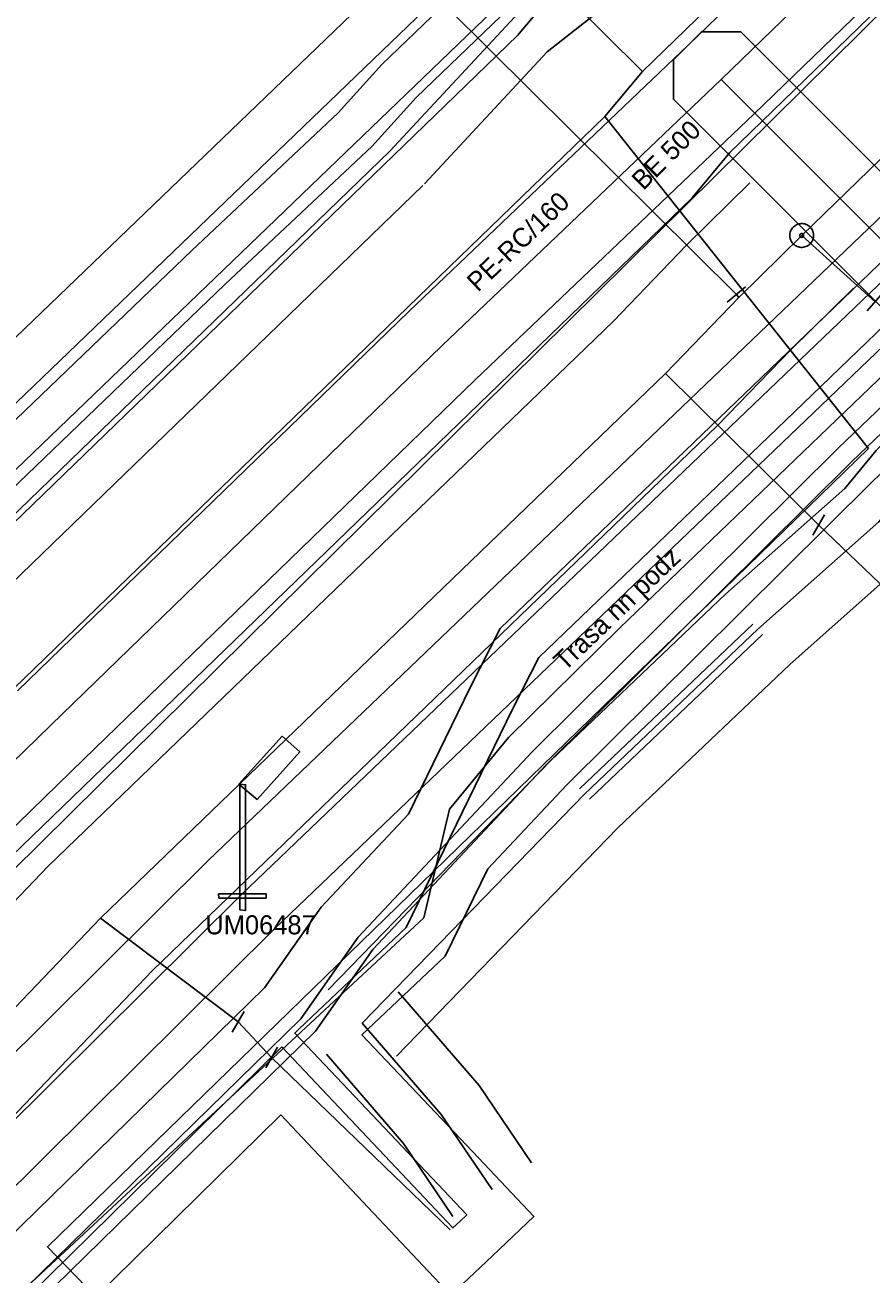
# Model space of a CAD drawing. Extents: x -762993 to -761845, y -975230 to -974501.
# Drawn here: x -762232.71 to -762214.93, y -974970.05 to -974943.8 of the extents above; entities that cross this region are included whole.
import ezdxf

# ---------------------------------------------------------------- set-up
doc = ezdxf.new("R2010")
doc.units = 0
for name, color, linetype in [('IS_CETIN_chranicka', 7, 'Continuous'), ('IS_CETIN_OP', 7, 'Continuous'), ('IS_CETIN_podzem metalika zam', 7, 'Continuous'), ('IS_CETIN_podzem optika zam', 7, 'Continuous'), ('IS_CEZ-D_anotace', 7, 'Continuous'), ('IS_CEZ-D_el vedeni NN podzem', 7, 'Continuous'), ('IS_CEZ-D_el vedeni VN podzem', 7, 'Continuous'), ('IS_CEZ-D_el vedeni VN podzem soubeh investice', 7, 'Continuous'), ('IS_CEZ-D_OP', 7, 'Continuous'), ('IS_CEZ-T_parovod', 7, 'Continuous'), ('IS_CEZ-T_parovod OP', 7, 'Continuous'), ('IS_DPmUL_OP', 7, 'Continuous'), ('IS_DPmUL_VO lampy', 7, 'Continuous'), ('IS_DPmUL_VO lampy anotace', 7, 'Continuous'), ('IS_DPmUL_VO vedeni podzem', 7, 'Continuous'), ('IS_GASNET_plyn NTL anotace', 7, 'Continuous'), ('IS_GASNET_plyn NTL pripojky', 7, 'Continuous'), ('IS_GASNET_plyn NTL rad', 7, 'Continuous'), ('IS_GASNET_plyn OP', 7, 'Continuous'), ('IS_SCVK_kanalizace anotace', 7, 'Continuous'), ('IS_SCVK_kanalizace jednotna', 7, 'Continuous'), ('IS_SCVK_vodovod OP', 7, 'Continuous'), ('IS_SCVK_vodovod pripojky', 7, 'Continuous'), ('IS_SCVK_vodovod privadec', 7, 'Continuous'), ('IS_SCVK_vodovod znaky', 7, 'Continuous'), ('IS_TPS_podzem metalika', 7, 'Continuous')]:
    doc.layers.add(name, color=color, linetype=linetype)

msp = doc.modelspace()

# ---------------------------------------------------------------- linework, layer by layer
at = {"layer": 'IS_CETIN_chranicka'}
for points in [[(-762221.053, -974959.841), (-762217.413, -974956.381)], [(-762220.847, -974960.059), (-762217.207, -974956.599)]]:
    msp.add_lwpolyline(points, dxfattribs=at)
at = {"layer": 'IS_CETIN_OP'}
for points in [[(-762240.314, -974959.621), (-762235.368, -974954.443), (-762229.198, -974948.525), (-762226.125, -974945.639), (-762225.209, -974944.624), (-762223.108, -974942.602)], [(-762220.029, -974943.012), (-762221.734, -974944.362), (-762224.313, -974947.13)], [(-762224.35, -974947.167), (-762239.502, -974961.816), (-762240.717, -974963.012), (-762243.097, -974965.371), (-762252.983, -974975.106)], [(-762211.533, -974949.489), (-762214.818, -974952.733), (-762215.481, -974953.533), (-762217.986, -974955.753), (-762221.653, -974959.239), (-762226.337, -974964.063)], [(-762210.127, -974950.911), (-762213.342, -974954.087), (-762214.039, -974954.927), (-762216.634, -974957.227), (-762220.247, -974960.661), (-762224.903, -974965.457)], [(-762224.864, -974964.106), (-762223.165, -974966.071), (-762222.062, -974967.699)], [(-762226.376, -974965.414), (-762224.755, -974967.289), (-762223.718, -974968.821)]]:
    msp.add_lwpolyline(points, dxfattribs=at)
at = {"layer": 'IS_CETIN_podzem metalika zam'}
for points in [[(-762220.718, -974942.282), (-762222.414, -974943.625), (-762225.045, -974946.448)], [(-762225.045, -974946.448), (-762240.2, -974961.1), (-762241.42, -974962.3), (-762243.8, -974964.66), (-762253.685, -974974.393)], [(-762225.62, -974964.76), (-762223.96, -974966.68), (-762222.89, -974968.26)]]:
    msp.add_lwpolyline(points, dxfattribs=at)
at = {"layer": 'IS_CETIN_podzem optika zam'}
for points in [[(-762240.2, -974960.95), (-762234.66, -974955.15), (-762228.51, -974949.25), (-762225.41, -974946.34), (-762224.49, -974945.32), (-762221.81, -974942.74)], [(-762210.83, -974950.2), (-762214.08, -974953.41), (-762214.76, -974954.23), (-762217.31, -974956.49), (-762220.95, -974959.95), (-762225.62, -974964.76)]]:
    msp.add_lwpolyline(points, dxfattribs=at)
at = {"layer": 'IS_CEZ-D_el vedeni NN podzem'}
for points in [[(-762247.847, -974984.536), (-762246.114, -974982.893), (-762246.05, -974980.697), (-762253.7, -974972.107), (-762252.057, -974970.493), (-762250.973, -974969.428), (-762239.791, -974958.41), (-762235.916, -974954.845), (-762234.541, -974953.31), (-762221.186, -974940.477), (-762220.991, -974940.306), (-762216.22, -974936.128), (-762203.456, -974923.483), (-762203.186, -974923.213), (-762202.673, -974922.708), (-762197.126, -974917.211), (-762182.367, -974902.622)], [(-762208.334, -974953.71), (-762208.48, -974953.847), (-762208.988, -974953.368), (-762212.916, -974949.013), (-762213.196, -974948.702), (-762213.301, -974948.803), (-762216.542, -974951.927), (-762221.91, -974957.079), (-762222.456, -974958.155), (-762224.696, -974962.752), (-762226.947, -974964.881), (-762227.041, -974964.97), (-762223.906, -974968.281), (-762223.426, -974968.788), (-762223.572, -974968.926)], [(-762223.572, -974968.926), (-762223.717, -974969.063), (-762224.197, -974968.555), (-762227.309, -974965.261), (-762240.713, -974978.438), (-762243.49, -974981.054), (-762244.149, -974981.659), (-762244.288, -974981.787), (-762243.667, -974982.434), (-762243.409, -974982.703), (-762244.131, -974983.395)]]:
    msp.add_lwpolyline(points, dxfattribs=at)
at = {"layer": 'IS_CEZ-D_el vedeni VN podzem'}
msp.add_lwpolyline([(-762178.94, -974917.38), (-762180.88, -974919.33), (-762183.85, -974922.18), (-762189.02, -974927.27), (-762191.6, -974929.28), (-762204.29, -974941.85), (-762215.61, -974952.68), (-762222.04, -974959.06), (-762225.71, -974962.96), (-762226.91, -974964.67), (-762236.89, -974974.42), (-762240.73, -974978.21), (-762245.09, -974982.81)], dxfattribs=at)
at = {"layer": 'IS_CEZ-D_el vedeni VN podzem soubeh investice'}
msp.add_lwpolyline([(-762246.655, -974985.018), (-762244.801, -974983.086), (-762240.444, -974978.49), (-762236.61, -974974.705), (-762226.604, -974964.93), (-762225.399, -974963.213), (-762221.753, -974959.339), (-762215.331, -974952.967), (-762204.011, -974942.137), (-762191.335, -974929.581), (-762188.756, -974927.571), (-762183.571, -974922.467), (-762180.6, -974919.615), (-762178.658, -974917.664), (-762169.2, -974908.366)], dxfattribs=at)
at = {"layer": 'IS_CEZ-D_OP'}
for points in [[(-762235.261, -974952.615), (-762221.862, -974939.74), (-762221.65, -974939.554), (-762216.902, -974935.396), (-762204.161, -974922.774), (-762203.89, -974922.503), (-762203.376, -974921.997), (-762197.829, -974916.5), (-762183.107, -974901.948), (-762182.738, -974901.004), (-762180.901, -974896.322), (-762175.443, -974882.405), (-762170.837, -974870.904), (-762171.08, -974867.387), (-762172.169, -974851.621), (-762173.361, -974831.196), (-762173.4, -974830.555), (-762173.438, -974829.89), (-762173.725, -974824.972), (-762174.311, -974821.59), (-762174.662, -974815.176), (-762174.624, -974813.433), (-762174.492, -974807.288)], [(-762252.034, -974971.872), (-762251.356, -974971.206), (-762250.272, -974970.141), (-762239.101, -974959.134), (-762235.203, -974955.548), (-762233.821, -974954.005), (-762220.51, -974941.214), (-762220.332, -974941.058), (-762215.538, -974936.86), (-762202.751, -974924.192), (-762202.482, -974923.923), (-762201.97, -974923.419), (-762196.423, -974917.922), (-762181.665, -974903.334)], [(-762212.335, -974948.163), (-762213.144, -974947.265), (-762213.995, -974948.083), (-762217.235, -974951.206), (-762222.725, -974956.475), (-762223.351, -974957.71), (-762224.65, -974960.374)], [(-762212.441, -974951.032), (-762214.912, -974953.396), (-762221.323, -974959.758), (-762222.985, -974961.523)], [(-762224.65, -974960.374), (-762226.487, -974962.327), (-762227.675, -974964.02), (-762237.591, -974973.706), (-762241.444, -974977.51), (-762244.368, -974980.594)], [(-762222.985, -974961.523), (-762223.877, -974963.354), (-762225.627, -974965.009), (-762223.18, -974967.593), (-762222.012, -974968.827), (-762222.885, -974969.653)], [(-762222.885, -974969.653), (-762223.757, -974970.477), (-762224.924, -974969.242), (-762227.335, -974966.689), (-762240.02, -974979.159), (-762242.183, -974981.196)]]:
    msp.add_lwpolyline(points, dxfattribs=at)
at = {"layer": 'IS_CEZ-T_parovod'}
for p, q in [((-762219.73, -974944.77), (-762227.14, -974937.44)), ((-762220.52, -974945.72), (-762214.98, -974952.69))]:
    msp.add_line(p, q, dxfattribs=at)
for points in [[(-762252.5, -975008.59), (-762252.58, -975007.19), (-762253.19, -974987.18), (-762253.2, -974985.67), (-762257.54, -974981.54), (-762246.7, -974971.01), (-762237.24, -974961.81), (-762238.76, -974960.21), (-762237.06, -974958.42), (-762235.35, -974960.05), (-762220.52, -974945.72), (-762219.73, -974944.77), (-762200.92, -974926.55), (-762198.18, -974929.41), (-762193.38, -974924.68)], [(-762214.98, -974952.69), (-762232.24, -974969.46), (-762228.39, -974973.44)]]:
    msp.add_lwpolyline(points, dxfattribs=at)
at = {"layer": 'IS_CEZ-T_parovod OP'}
for points in [[(-762254.996, -975008.733), (-762255.078, -975007.299), (-762255.69, -974987.226), (-762255.693, -974986.749), (-762261.147, -974981.559), (-762248.442, -974969.217), (-762240.754, -974961.74), (-762242.208, -974960.21), (-762237.148, -974954.882), (-762235.362, -974956.585), (-762222.355, -974944.017), (-762221.566, -974943.068), (-762200.854, -974923.005), (-762198.129, -974925.85), (-762195.116, -974922.881)], [(-762250.004, -975008.447), (-762250.082, -975007.081), (-762250.69, -974987.134), (-762250.707, -974984.591), (-762253.933, -974981.521), (-762244.958, -974972.803), (-762235.373, -974963.482), (-762235.338, -974963.515), (-762218.685, -974947.423), (-762217.894, -974946.472), (-762200.986, -974930.095), (-762198.231, -974932.97), (-762193.371, -974928.181)]]:
    msp.add_lwpolyline(points, dxfattribs=at)
at = {"layer": 'IS_DPmUL_OP'}
for p, q in [((-762228.861, -974961.348), (-762208.613, -974941.975)), ((-762227.465, -974962.78), (-762207.231, -974943.421)), ((-762244.874, -974977.229), (-762228.861, -974961.348)), ((-762243.466, -974978.649), (-762227.465, -974962.78))]:
    msp.add_line(p, q, dxfattribs=at)
at = {"layer": 'IS_DPmUL_VO lampy'}
for points in [[(-762227.303, -974958.734), (-762226.933, -974959.064), (-762227.833, -974960.064), (-762228.213, -974959.744)], [(-762228.193, -974959.744), (-762228.073, -974959.754), (-762228.073, -974962.394), (-762228.193, -974962.384)], [(-762228.643, -974962.044), (-762227.643, -974962.044), (-762227.643, -974962.134), (-762228.633, -974962.134)]]:
    msp.add_lwpolyline(points, close=True, dxfattribs=at)
at = {"layer": 'IS_DPmUL_VO vedeni podzem'}
for points in [[(-762228.163, -974962.064), (-762207.922, -974942.698)], [(-762244.17, -974977.939), (-762228.163, -974962.064)]]:
    msp.add_lwpolyline(points, dxfattribs=at)
at = {"layer": 'IS_GASNET_plyn NTL pripojky'}
msp.add_lwpolyline([(-762218.08, -974944.94), (-762211.6, -974951.42)], dxfattribs=at)
at = {"layer": 'IS_GASNET_plyn NTL rad'}
msp.add_lwpolyline([(-762254.38, -974980.34), (-762254.3, -974980.18), (-762254.49, -974979.97), (-762249.33, -974975.11), (-762246.79, -974972.7), (-762240.45, -974966.56), (-762232.17, -974958.5), (-762223.94, -974950.53), (-762218.08, -974944.94), (-762212.07, -974939.13), (-762200.83, -974928.57), (-762199.24, -974927.03), (-762198.4, -974925.79), (-762191.542, -974918.748)], dxfattribs=at)
at = {"layer": 'IS_GASNET_plyn OP'}
for points in [[(-762232.867, -974957.783), (-762224.633, -974949.809), (-762218.773, -974944.219), (-762212.76, -974938.406)], [(-762211.38, -974939.854), (-762217.387, -974945.661), (-762223.247, -974951.251), (-762231.473, -974959.217), (-762239.753, -974967.277)]]:
    msp.add_lwpolyline(points, dxfattribs=at)
msp.add_lwpolyline([(-762217.666, -974943.94), (-762217.373, -974944.233), (-762210.893, -974950.713), (-762210.6, -974951.006), (-762210.6, -974951.834), (-762210.893, -974952.127), (-762211.186, -974952.42), (-762212.014, -974952.42), (-762212.307, -974952.127), (-762218.787, -974945.647), (-762219.08, -974945.354), (-762219.08, -974944.526), (-762218.787, -974944.233), (-762218.494, -974943.94)], close=True, dxfattribs=at)
at = {"layer": 'IS_SCVK_kanalizace jednotna'}
msp.add_lwpolyline([(-762237.305, -974965.834), (-762203.442, -974932.379)], dxfattribs=at)
at = {"layer": 'IS_SCVK_vodovod OP'}
for points in [[(-762217.473, -974947.113), (-762218.81, -974948.43), (-762220.343, -974950.02), (-762232.223, -974961.467), (-762242.519, -974972.237), (-762258.353, -974987.594)], [(-762215.297, -974949.321), (-762216.606, -974950.61), (-762218.151, -974952.212), (-762230.027, -974963.655), (-762240.319, -974974.421), (-762256.335, -974989.956)]]:
    msp.add_lwpolyline(points, dxfattribs=at)
at = {"layer": 'IS_SCVK_vodovod pripojky'}
for points in [[(-762217.757, -974949.459), (-762223.825, -974943.439)], [(-762219.247, -974951.116), (-762216.028, -974954.299)], [(-762216.028, -974954.299), (-762213.626, -974956.595)], [(-762231.125, -974962.561), (-762228.228, -974964.735)], [(-762228.228, -974964.735), (-762227.526, -974965.482)], [(-762227.526, -974965.482), (-762223.772, -974969.102)]]:
    msp.add_lwpolyline(points, dxfattribs=at)
at = {"layer": 'IS_SCVK_vodovod privadec'}
for points in [[(-762201.113, -974933.408), (-762202.03, -974934.3), (-762216.385, -974948.217)], [(-762216.385, -974948.217), (-762217.708, -974949.52), (-762219.247, -974951.116), (-762231.125, -974962.561), (-762241.419, -974973.329), (-762257.344, -974988.775)], [(-762216.385, -974948.217), (-762214.841, -974949.611)]]:
    msp.add_lwpolyline(points, dxfattribs=at)
at = {"layer": 'IS_SCVK_vodovod znaky'}
for points in [[(-762216.206, -974948.043), (-762216.225, -974948.025), (-762216.246, -974948.009), (-762216.268, -974947.996), (-762216.292, -974947.985), (-762216.317, -974947.976), (-762216.342, -974947.971), (-762216.368, -974947.968), (-762216.394, -974947.968), (-762216.42, -974947.97), (-762216.446, -974947.975), (-762216.471, -974947.982), (-762216.495, -974947.993), (-762216.518, -974948.005), (-762216.539, -974948.02), (-762216.559, -974948.038), (-762216.577, -974948.057), (-762216.593, -974948.078), (-762216.606, -974948.1), (-762216.617, -974948.124), (-762216.625, -974948.149), (-762216.631, -974948.174), (-762216.634, -974948.2), (-762216.635, -974948.226), (-762216.633, -974948.252), (-762216.627, -974948.278), (-762216.62, -974948.303), (-762216.609, -974948.327), (-762216.596, -974948.35), (-762216.582, -974948.371), (-762216.564, -974948.391), (-762216.545, -974948.409), (-762216.524, -974948.425), (-762216.502, -974948.438), (-762216.478, -974948.449), (-762216.453, -974948.457), (-762216.428, -974948.463), (-762216.402, -974948.467), (-762216.376, -974948.467), (-762216.35, -974948.465), (-762216.324, -974948.459), (-762216.299, -974948.452), (-762216.275, -974948.442), (-762216.252, -974948.429), (-762216.231, -974948.414), (-762216.211, -974948.396), (-762216.193, -974948.377), (-762216.177, -974948.356), (-762216.164, -974948.334), (-762216.153, -974948.31), (-762216.145, -974948.285), (-762216.139, -974948.26), (-762216.136, -974948.234), (-762216.135, -974948.208), (-762216.138, -974948.182), (-762216.143, -974948.156), (-762216.15, -974948.131), (-762216.16, -974948.107), (-762216.173, -974948.084), (-762216.188, -974948.062), (-762216.206, -974948.043)], [(-762216.356, -974948.188), (-762216.359, -974948.185), (-762216.362, -974948.183), (-762216.366, -974948.181), (-762216.37, -974948.179), (-762216.373, -974948.177), (-762216.378, -974948.177), (-762216.382, -974948.176), (-762216.386, -974948.176), (-762216.39, -974948.177), (-762216.395, -974948.177), (-762216.399, -974948.179), (-762216.403, -974948.18), (-762216.407, -974948.182), (-762216.41, -974948.184), (-762216.414, -974948.188), (-762216.417, -974948.191), (-762216.419, -974948.194), (-762216.421, -974948.198), (-762216.422, -974948.202), (-762216.424, -974948.206), (-762216.425, -974948.21), (-762216.426, -974948.214), (-762216.426, -974948.218), (-762216.426, -974948.223), (-762216.425, -974948.226), (-762216.423, -974948.231), (-762216.422, -974948.235), (-762216.42, -974948.239), (-762216.417, -974948.242), (-762216.414, -974948.246), (-762216.411, -974948.249), (-762216.408, -974948.251), (-762216.404, -974948.253), (-762216.4, -974948.255), (-762216.396, -974948.256), (-762216.392, -974948.258), (-762216.388, -974948.258), (-762216.383, -974948.258), (-762216.378, -974948.258), (-762216.375, -974948.257), (-762216.371, -974948.255), (-762216.367, -974948.253), (-762216.363, -974948.252), (-762216.36, -974948.25), (-762216.356, -974948.246), (-762216.353, -974948.243), (-762216.351, -974948.24), (-762216.349, -974948.236), (-762216.347, -974948.232), (-762216.346, -974948.228), (-762216.344, -974948.224), (-762216.344, -974948.22), (-762216.344, -974948.216), (-762216.345, -974948.211), (-762216.345, -974948.207), (-762216.346, -974948.203), (-762216.348, -974948.199), (-762216.35, -974948.195), (-762216.352, -974948.192), (-762216.356, -974948.188)], [(-762217.565, -974949.299), (-762217.949, -974949.619)], [(-762217.708, -974949.52), (-762217.757, -974949.459)], [(-762214.676, -974949.424), (-762215.007, -974949.798)], [(-762215.903, -974954.082), (-762216.153, -974954.515)], [(-762228.103, -974964.518), (-762228.353, -974964.951)], [(-762227.401, -974965.265), (-762227.651, -974965.698)]]:
    msp.add_lwpolyline(points, dxfattribs=at)
at = {"layer": 'IS_TPS_podzem metalika'}
msp.add_lwpolyline([(-762172.29, -974910.28), (-762185.23, -974922.87), (-762190.46, -974927.24), (-762198, -974934.74), (-762201.39, -974938.15), (-762206.9, -974943.61), (-762214.43, -974950.91), (-762220.21, -974956.46), (-762222.55, -974958.76), (-762223.79, -974960.27), (-762224.33, -974962.55), (-762233.162, -974970.759), (-762240.486, -974977.956), (-762246.238, -974984.004)], dxfattribs=at)

# ---------------------------------------------------------------- texts
at = {"layer": 'IS_CEZ-D_anotace'}
msp.add_text('Trasa nn podz', height=0.4, rotation=43.8238, dxfattribs=at).set_placement((-762221.363, -974957.386))
at = {"layer": 'IS_DPmUL_VO lampy anotace'}
msp.add_text('UM06487', height=0.4, dxfattribs=at).set_placement((-762228.919, -974962.897))
at = {"layer": 'IS_GASNET_plyn NTL anotace'}
msp.add_text('PE-RC/160', height=0.4, rotation=43.6492, dxfattribs=at).set_placement((-762223.188, -974949.422))
at = {"layer": 'IS_SCVK_kanalizace anotace'}
msp.add_text('BE 500', height=0.4, rotation=45, dxfattribs=at).set_placement((-762219.713, -974947.283))

doc.saveas('drawing.dxf')
